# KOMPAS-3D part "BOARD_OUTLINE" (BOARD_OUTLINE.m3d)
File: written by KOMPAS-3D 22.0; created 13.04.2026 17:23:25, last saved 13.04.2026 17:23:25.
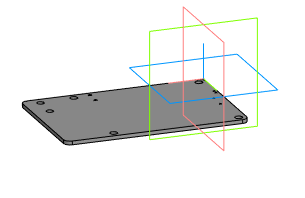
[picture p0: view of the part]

Document properties: Автор: Andrey; Полное имя файла: C:\Users\User1\Documents\BOARD_OUTLINE.m3d

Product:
- Part/product: BOARD_OUTLINE
    Комментарий: BOARD_OUTLINE

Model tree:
1. Операция без истории:1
